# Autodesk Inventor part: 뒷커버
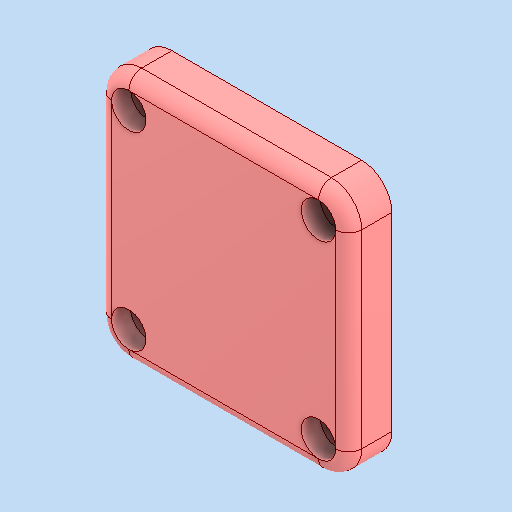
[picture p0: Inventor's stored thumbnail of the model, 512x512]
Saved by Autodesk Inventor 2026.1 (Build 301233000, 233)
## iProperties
Created: 2026-01
Part Number: 뒷커버
Material: 알루미늄 6061
Document SubType Name: Modeling
Designer: PC-30
Density: 2.7 g/cm^3
Appearance: 기본값
Author: jhkim
Sending System: Autodesk Inventor 2026
Preprocessor: ST-DEVELOPER v20.1
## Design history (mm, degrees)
feature "솔리드1"
node "솔리드2"
